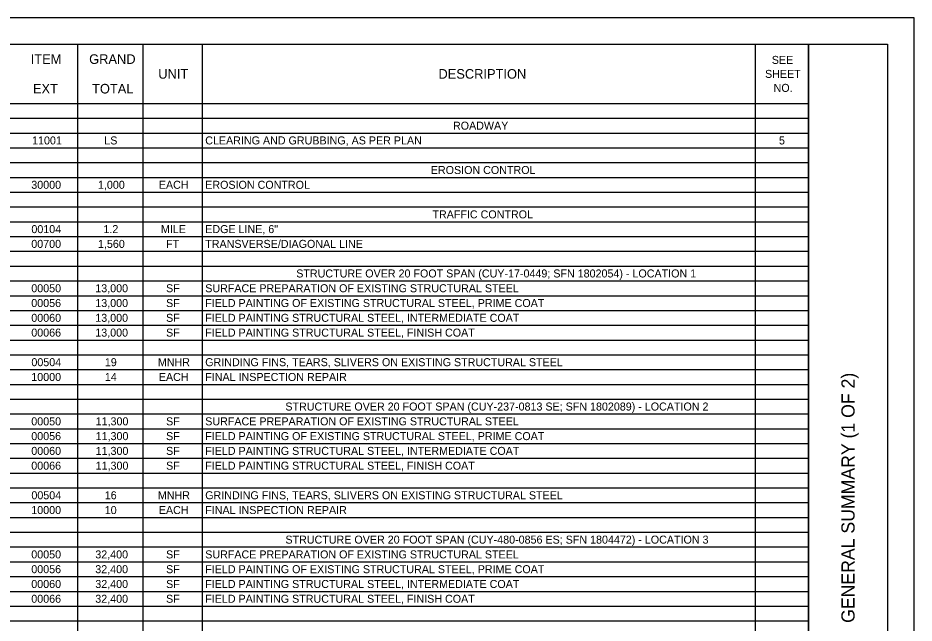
# Model space of a CAD drawing. Extents: x 0 to 34, y 0 to 22.
# Drawn here: x 17.04 to 34, y 10.54 to 22 of the extents above; entities that cross this region are included whole.
import ezdxf

# ---------------------------------------------------------------- set-up
doc = ezdxf.new("R2010")
doc.units = 0
for name, color, linetype in [('SH_Border', 7, 'Continuous'), ('SH_Cut_Line', 7, 'Continuous'), ('SH_Data', 7, 'Continuous'), ('SH_Text', 7, 'Continuous')]:
    doc.layers.add(name, color=color, linetype=linetype)

msp = doc.modelspace()

# ---------------------------------------------------------------- linework, layer by layer
at = {"layer": 'SH_Border'}
msp.add_line((32, 0.5), (32, 21.5), dxfattribs=at)
msp.add_lwpolyline([(1.5, 21.5), (33.5, 21.5), (33.5, 0.5), (1.5, 0.5)], close=True, dxfattribs=at)
at = {"layer": 'SH_Cut_Line'}
msp.add_lwpolyline([(0, 0), (34, 0), (34, 22), (0, 22)], close=True, dxfattribs=at)
at = {"layer": 'SH_Text'}
for p, q in [((1.5, 21.5), (32, 21.5)), ((18.173, 21.5), (18.173, 0.502)), ((19.409, 21.5), (19.409, 0.502)), ((20.53, 21.5), (20.53, 0.502)), ((30.994, 21.5), (30.994, 0.502)), ((32, 21.5), (32, 0.502)), ((1.5, 20.38), (32, 20.38)), ((1.5, 20.1), (32, 20.1)), ((1.5, 19.82), (32, 19.82)), ((1.5, 19.54), (32, 19.54)), ((1.5, 19.26), (32, 19.26)), ((1.5, 18.98), (32, 18.98)), ((1.5, 18.7), (32, 18.7)), ((1.5, 18.42), (32, 18.42)), ((1.5, 18.14), (32, 18.14)), ((1.5, 17.86), (32, 17.86)), ((1.5, 17.58), (32, 17.58)), ((1.5, 17.3), (32, 17.3)), ((1.5, 17.02), (32, 17.02)), ((1.5, 16.74), (32, 16.74)), ((1.5, 16.46), (32, 16.46)), ((1.5, 16.18), (32, 16.18)), ((1.5, 15.9), (32, 15.9)), ((1.5, 15.62), (32, 15.62)), ((1.5, 15.34), (32, 15.34)), ((1.5, 15.061), (32, 15.061)), ((1.5, 14.781), (32, 14.781)), ((1.5, 14.501), (32, 14.501)), ((1.5, 14.221), (32, 14.221)), ((1.5, 13.941), (32, 13.941)), ((1.5, 13.661), (32, 13.661)), ((1.5, 13.381), (32, 13.381)), ((1.5, 13.101), (32, 13.101)), ((1.5, 12.821), (32, 12.821)), ((1.5, 12.541), (32, 12.541)), ((1.5, 12.261), (32, 12.261)), ((1.5, 11.981), (32, 11.981)), ((1.5, 11.701), (32, 11.701)), ((1.5, 11.421), (32, 11.421)), ((1.5, 11.141), (32, 11.141)), ((1.5, 10.861), (32, 10.861)), ((1.5, 10.581), (32, 10.581))]:
    msp.add_line(p, q, dxfattribs=at)

# ---------------------------------------------------------------- texts
at = {"layer": 'SH_Data'}
msp.add_text('GENERAL SUMMARY (1 OF 2)', height=0.25, rotation=90, dxfattribs=at).set_placement((32.875, 10.544))
at = {"layer": 'SH_Text'}
for s, height, p in [('ITEM', 0.1818, (17.286, 21.129)), ('GRAND', 0.1818, (18.392, 21.129)), ('SEE ', 0.1515, (31.308, 21.129)), ('UNIT', 0.1818, (19.7, 20.849)), ('DESCRIPTION', 0.18182, (25.001, 20.849)), ('SHEET ', 0.1515, (31.18, 20.864)), ('EXT', 0.1818, (17.328, 20.569)), ('TOTAL', 0.1818, (18.447, 20.569)), ('NO.', 0.1515, (31.342, 20.599)), ('ROADWAY', 0.1515, (25.276, 19.884)), ('11001', 0.1515, (17.312, 19.604)), ('LS', 0.1515, (18.678, 19.604)), ('CLEARING AND GRUBBING, AS PER PLAN', 0.15152, (20.588, 19.604)), ('5', 0.152, (31.444, 19.604)), ('EROSION CONTROL', 0.15152, (24.856, 19.044)), ('30000', 0.1515, (17.297, 18.764)), ('1,000', 0.1515, (18.559, 18.764)), ('EACH', 0.1515, (19.71, 18.764)), ('EROSION CONTROL', 0.15152, (20.588, 18.764)), ('TRAFFIC CONTROL', 0.15152, (24.887, 18.204)), ('00104', 0.1515, (17.299, 17.925)), ('1.2', 0.1515, (18.662, 17.925)), ('MILE', 0.1515, (19.75, 17.925)), ('EDGE LINE, 6"', 0.15152, (20.588, 17.925)), ('TRANSVERSE/DIAGONAL LINE', 0.15152, (20.588, 17.645)), ('00700', 0.1515, (17.297, 17.645)), ('1,560', 0.1515, (18.559, 17.645)), ('FT', 0.1515, (19.848, 17.645)), ('STRUCTURE OVER 20 FOOT SPAN (CUY-17-0449; SFN 1802054) - LOCATION 1', 0.15152, (22.31, 17.085)), ('00050', 0.1515, (17.297, 16.805)), ('13,000', 0.1515, (18.508, 16.805)), ('SF', 0.1515, (19.847, 16.805)), ('SURFACE PREPARATION OF EXISTING STRUCTURAL STEEL', 0.15152, (20.588, 16.805)), ('00056', 0.1515, (17.297, 16.525)), ('13,000', 0.1515, (18.508, 16.525)), ('SF', 0.1515, (19.847, 16.525)), ('FIELD PAINTING OF EXISTING STRUCTURAL STEEL, PRIME COAT', 0.15152, (20.588, 16.525)), ('00060', 0.1515, (17.297, 16.245)), ('13,000', 0.1515, (18.508, 16.245)), ('SF', 0.1515, (19.847, 16.245)), ('FIELD PAINTING STRUCTURAL STEEL, INTERMEDIATE COAT', 0.15152, (20.588, 16.245)), ('00066', 0.1515, (17.297, 15.965)), ('13,000', 0.1515, (18.508, 15.965)), ('SF', 0.1515, (19.847, 15.965)), ('FIELD PAINTING STRUCTURAL STEEL, FINISH COAT', 0.15152, (20.588, 15.965)), ('00504', 0.1515, (17.299, 15.405)), ('19', 0.1515, (18.689, 15.405)), ('MNHR', 0.1515, (19.692, 15.405)), ('GRINDING FINS, TEARS, SLIVERS ON EXISTING STRUCTURAL STEEL', 0.15152, (20.588, 15.405)), ('10000', 0.1515, (17.297, 15.125)), ('14', 0.1515, (18.689, 15.125)), ('EACH', 0.1515, (19.71, 15.125)), ('FINAL INSPECTION REPAIR', 0.15152, (20.588, 15.125)), ('STRUCTURE OVER 20 FOOT SPAN (CUY-237-0813 SE; SFN 1802089) - LOCATION 2', 0.15152, (22.104, 14.565)), ('00050', 0.1515, (17.297, 14.285)), ('11,300', 0.1515, (18.515, 14.285)), ('SF', 0.1515, (19.847, 14.285)), ('SURFACE PREPARATION OF EXISTING STRUCTURAL STEEL', 0.15152, (20.588, 14.285)), ('00056', 0.1515, (17.297, 14.005)), ('11,300', 0.1515, (18.515, 14.005)), ('SF', 0.1515, (19.847, 14.005)), ('FIELD PAINTING OF EXISTING STRUCTURAL STEEL, PRIME COAT', 0.15152, (20.588, 14.005)), ('00060', 0.1515, (17.297, 13.725)), ('11,300', 0.1515, (18.515, 13.725)), ('SF', 0.1515, (19.847, 13.725)), ('FIELD PAINTING STRUCTURAL STEEL, INTERMEDIATE COAT', 0.15152, (20.588, 13.725)), ('00066', 0.1515, (17.297, 13.445)), ('11,300', 0.1515, (18.515, 13.445)), ('SF', 0.1515, (19.847, 13.445)), ('FIELD PAINTING STRUCTURAL STEEL, FINISH COAT', 0.15152, (20.588, 13.445)), ('00504', 0.1515, (17.299, 12.885)), ('16', 0.1515, (18.687, 12.885)), ('MNHR', 0.1515, (19.692, 12.885)), ('GRINDING FINS, TEARS, SLIVERS ON EXISTING STRUCTURAL STEEL', 0.15152, (20.588, 12.885)), ('10000', 0.1515, (17.297, 12.605)), ('10', 0.1515, (18.687, 12.605)), ('EACH', 0.1515, (19.71, 12.605)), ('FINAL INSPECTION REPAIR', 0.15152, (20.588, 12.605)), ('STRUCTURE OVER 20 FOOT SPAN (CUY-480-0856 ES; SFN 1804472) - LOCATION 3', 0.15152, (22.105, 12.045)), ('00050', 0.1515, (17.297, 11.765)), ('32,400', 0.1515, (18.508, 11.765)), ('SF', 0.1515, (19.847, 11.765)), ('SURFACE PREPARATION OF EXISTING STRUCTURAL STEEL', 0.15152, (20.588, 11.765)), ('00056', 0.1515, (17.297, 11.485)), ('32,400', 0.1515, (18.508, 11.485)), ('SF', 0.1515, (19.847, 11.485)), ('FIELD PAINTING OF EXISTING STRUCTURAL STEEL, PRIME COAT', 0.15152, (20.588, 11.485)), ('00060', 0.1515, (17.297, 11.205)), ('32,400', 0.1515, (18.508, 11.205)), ('SF', 0.1515, (19.847, 11.205)), ('FIELD PAINTING STRUCTURAL STEEL, INTERMEDIATE COAT', 0.15152, (20.588, 11.205)), ('00066', 0.1515, (17.297, 10.925)), ('32,400', 0.1515, (18.508, 10.925)), ('SF', 0.1515, (19.847, 10.925)), ('FIELD PAINTING STRUCTURAL STEEL, FINISH COAT', 0.15152, (20.588, 10.925))]:
    msp.add_text(s, height=height, dxfattribs=at).set_placement(p)

doc.saveas('drawing.dxf')
